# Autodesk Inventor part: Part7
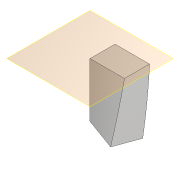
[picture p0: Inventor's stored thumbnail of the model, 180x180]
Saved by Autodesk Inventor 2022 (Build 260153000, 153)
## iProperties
Created: 2015-07
Part Number: Part7
Material: Generic
Document SubType Name: Modeling
Designer: Sandeep
Density: 1 g/cm^3
Appearance: Default
Author: Sandeep
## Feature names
1. Sweep1
## Parameters: d0 = 0, d1 = 20 deg
